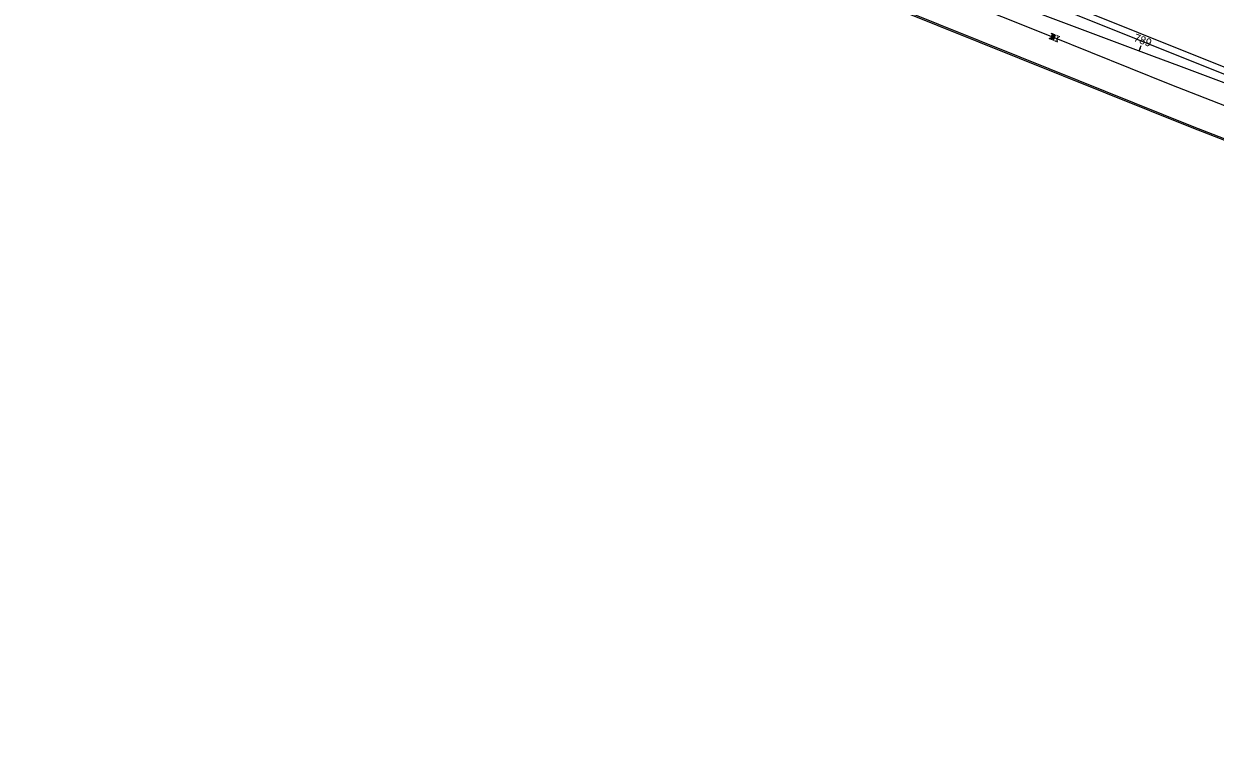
# Model space of a CAD drawing. Extents: x 2349621 to 2352073, y 625611 to 626553.
# Drawn here: x 2350956.3 to 2351373.1, y 625611.7 to 625866.1 of the extents above; entities that cross this region are included whole.
import ezdxf

# ---------------------------------------------------------------- set-up
doc = ezdxf.new("R2010")
doc.units = 0
for name, color, linetype in [('PM_X_Cells', 7, 'Continuous'), ('PM_X_Edge_Line', 7, 'Continuous'), ('PM_X_Lane_Line', 7, 'Continuous'), ('PV_X_EOP', 7, 'Continuous'), ('RW_X_CL', 7, 'Continuous'), ('RW_X_CL_100_Stations', 7, 'Continuous'), ('RW_X_CL_500_Stations', 7, 'Continuous')]:
    doc.layers.add(name, color=color, linetype=linetype)

msp = doc.modelspace()

# ---------------------------------------------------------------- linework, layer by layer
at = {"layer": 'PM_X_Cells'}
for p, q in [((2351315.05, 625860.99), (2351315.42, 625860.84)), ((2351315.43, 625860.83), (2351315.33, 625861.07)), ((2351315.85, 625860.66), (2351315.6, 625861.25)), ((2351315.67, 625860.73), (2351316.04, 625860.58)), ((2351315.78, 625862.8), (2351316.16, 625862.65)), ((2351316.27, 625860.49), (2351315.83, 625861.52)), ((2351316.56, 625860.62), (2351315.99, 625861.96)), ((2351316.73, 625861.03), (2351316.03, 625862.7)), ((2351316.29, 625860.48), (2351316.67, 625860.33)), ((2351316.41, 625862.54), (2351316.78, 625862.39)), ((2351316.9, 625861.45), (2351316.45, 625862.53)), ((2351316.48, 625860.41), (2351317.21, 625862.22)), ((2351316.85, 625861.31), (2351316.85, 625861.31)), ((2351317.07, 625861.87), (2351316.87, 625862.36)), ((2351316.92, 625860.23), (2351317.29, 625860.08)), ((2351317.03, 625862.29), (2351317.4, 625862.14)), ((2351317.54, 625859.98), (2351317.91, 625859.83)), ((2351317.65, 625862.04), (2351318.02, 625861.89)), ((2351318.27, 625861.79), (2351318.64, 625861.64))]:
    msp.add_line(p, q, dxfattribs=at)
for centre, start, end in [((2351314.85, 625862.12), 279.8966, 295.8433), ((2351314.85, 625862.12), 303.101, 319.0339), ((2351314.85, 625862.12), 20.0075, 35.9489), ((2351314.85, 625862.12), 326.3132, 349.543), ((2351314.85, 625862.12), 356.8106, 12.7435), ((2351318.84, 625860.5), 176.81, 192.7435), ((2351318.84, 625860.5), 146.3043, 169.5319), ((2351318.84, 625860.5), 200.0045, 215.9489), ((2351318.84, 625860.5), 123.101, 139.0326), ((2351318.84, 625860.5), 99.8966, 115.8391)]:
    msp.add_arc(centre, 1.15, start, end, dxfattribs=at)
at = {"layer": 'PM_X_Edge_Line'}
for points in [[(2350963.74, 626014.89), (2351032.32, 625987.17), (2351095.71, 625962.07), (2351152.54, 625939.23), (2351209.68, 625916.15), (2351265.03, 625893.7), (2351303.58, 625877.76), (2351345.44, 625860.89), (2351387.6, 625843.99), (2351430.99, 625827.11), (2351474.75, 625810.9), (2351502.4, 625801.12), (2351535.69, 625789.35), (2351577.68, 625775.6), (2351622.58, 625760.66), (2351663.85, 625747.4), (2351714.74, 625729.84), (2351764.19, 625714.28), (2351799.77, 625703.13), (2351848.31, 625686.82), (2351889.58, 625673.56), (2351936.76, 625658.21), (2351982.15, 625643.49)], [(2351976.42, 625623.21), (2351920.83, 625640.97), (2351841.95, 625666.41), (2351777.12, 625687.69), (2351724.25, 625705.24), (2351652.33, 625728.98), (2351591.84, 625748.83), (2351555.08, 625760.87), (2351507.03, 625777.09), (2351478.29, 625787.21), (2351423.53, 625807.58), (2351365.19, 625830.22), (2351304.85, 625854.49), (2351247.93, 625877.37), (2351203.89, 625894.92), (2351143.43, 625919.65), (2351117.74, 625929.97), (2351079.36, 625945.33), (2351042.9, 625960.12), (2351003.33, 625976.06), (2350965.81, 625991.28), (2350956.45, 625995.04)]]:
    msp.add_lwpolyline(points, dxfattribs=at)
at = {"layer": 'PM_X_Lane_Line'}
msp.add_lwpolyline([(2350960.41, 626005.5), (2351002.64, 625988.3), (2351066, 625962.88), (2351136.34, 625934.22), (2351210.8, 625903.65), (2351315.64, 625861.8), (2351357.25, 625845.01), (2351429.58, 625816.81), (2351493.91, 625793.24), (2351605.6, 625755.44), (2351685.16, 625729.5), (2351789.05, 625695.46), (2351865.04, 625671.13), (2351976.54, 625634.71)], dxfattribs=at)
at = {"layer": 'PV_X_EOP'}
for points in [[(2351982.85, 625645.63), (2351937.46, 625660.36), (2351890.28, 625675.71), (2351849.01, 625688.96), (2351800.47, 625705.27), (2351764.87, 625716.44), (2351715.44, 625731.98), (2351664.57, 625749.54), (2351623.28, 625762.81), (2351578.39, 625777.74), (2351536.41, 625791.49), (2351503.15, 625803.24), (2351475.52, 625813.02), (2351431.79, 625829.22), (2351388.43, 625846.09), (2351346.28, 625862.98), (2351304.44, 625879.85), (2351265.89, 625895.79), (2351210.53, 625918.24), (2351153.38, 625941.32), (2351096.55, 625964.17), (2351033.16, 625989.26), (2350964.49, 626017.02)], [(2351976.27, 625622.73), (2351920.68, 625640.49), (2351841.8, 625665.93), (2351776.97, 625687.21), (2351724.09, 625704.77), (2351652.18, 625728.51), (2351591.68, 625748.36), (2351554.93, 625760.4), (2351506.86, 625776.62), (2351478.12, 625786.74), (2351423.35, 625807.11), (2351365, 625829.75), (2351304.66, 625854.02), (2351247.74, 625876.9), (2351203.71, 625894.46), (2351143.24, 625919.19), (2351117.55, 625929.5), (2351079.17, 625944.86), (2351042.71, 625959.65), (2351003.14, 625975.6), (2350965.62, 625990.82), (2350956.27, 625994.57)]]:
    msp.add_lwpolyline(points, dxfattribs=at)
at = {"layer": 'RW_X_CL'}
msp.add_arc((2356442.68, 639481.86), 14547.12, 247.922783, 252.452173, dxfattribs=at)
at = {"layer": 'RW_X_CL_100_Stations'}
msp.add_line((2351346.51, 625856.6), (2351347.21, 625858.47), dxfattribs=at)
at = {"layer": 'RW_X_CL_500_Stations'}
msp.add_line((2351346.51, 625856.6), (2351346.93, 625857.72), dxfattribs=at)

# ---------------------------------------------------------------- texts
at = {"layer": 'RW_X_CL_100_Stations'}
msp.add_text('789', height=2.8, rotation=339.493, dxfattribs=at).set_placement((2351344.35, 625860.13))

doc.saveas('drawing.dxf')
